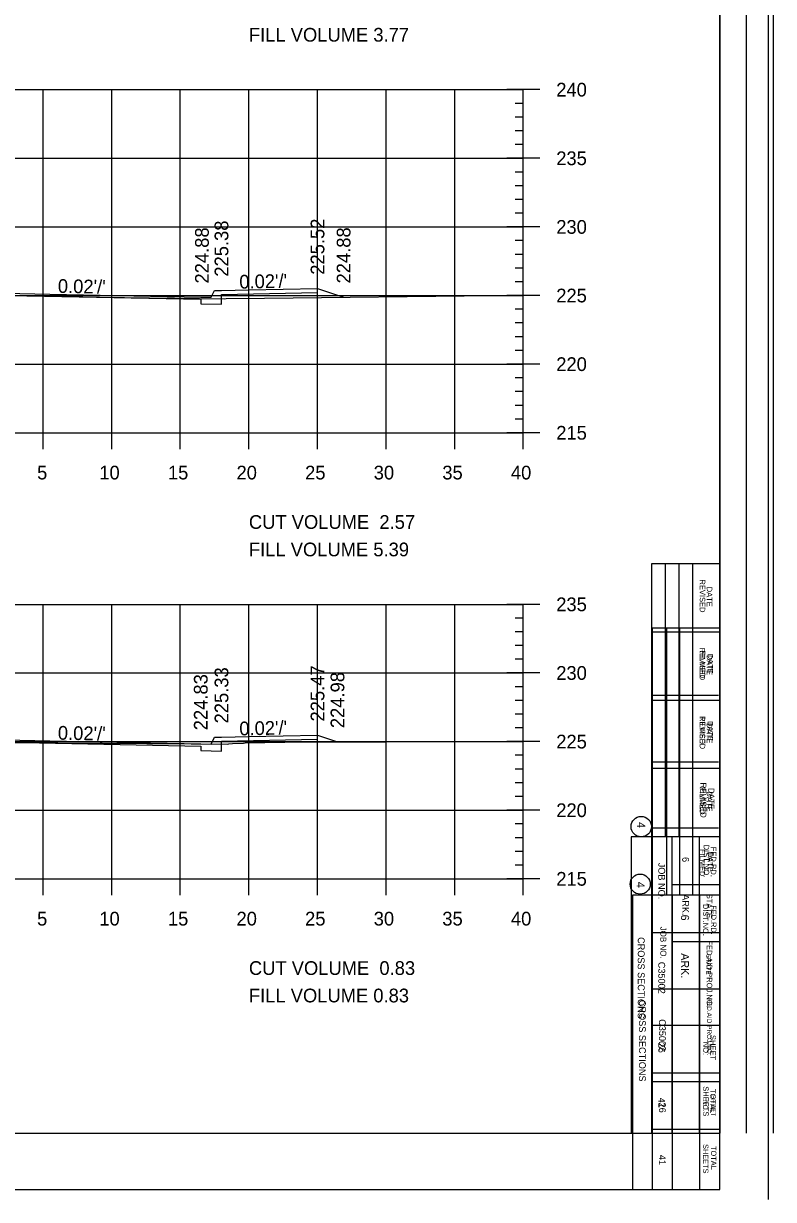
# Model space of a CAD drawing. Extents: x 1367903 to 1373764, y 376865 to 382130.
# Drawn here: x 1370086.4 to 1370195.7, y 377279.1 to 377450.5 of the extents above; entities that cross this region are included whole.
import ezdxf

# ---------------------------------------------------------------- set-up
doc = ezdxf.new("R2010")
doc.units = 0
for name, color, linetype in [('R_Axis', 7, 'Continuous'), ('R_Axis Annot', 7, 'Continuous'), ('R_Border', 7, 'Continuous'), ('R_Border Notes', 7, 'Continuous'), ('R_Border PE', 7, 'Continuous'), ('R_Exist Surface', 7, 'Continuous'), ('R_Fin Surface', 7, 'Continuous'), ('R_Fin Surface Annot', 7, 'Continuous'), ('R_Grid', 7, 'Continuous')]:
    doc.layers.add(name, color=color, linetype=linetype)

msp = doc.modelspace()

# ---------------------------------------------------------------- linework, layer by layer
for points in [[(1370043.22, 377411.59), (1370043.22, 377410.92), (1370043.22, 377410.92), (1370043.22, 377409.56), (1370046.22, 377409.62), (1370046.22, 377410.29), (1370079.22, 377410.95), (1370112.22, 377410.29), (1370112.22, 377409.62), (1370115.22, 377409.56), (1370115.22, 377411), (1370129.22, 377411.28), (1370129.22, 377411.87)], [(1370043.22, 377346.49), (1370043.22, 377345.82), (1370043.22, 377345.82), (1370043.22, 377344.46), (1370046.22, 377344.52), (1370046.22, 377345.18), (1370079.22, 377345.84), (1370112.22, 377345.18), (1370112.22, 377344.52), (1370115.22, 377344.46), (1370115.22, 377345.9), (1370129.22, 377346.18), (1370129.22, 377346.77)]]:
    msp.add_lwpolyline(points)
at = {"layer": 'R_Axis'}
for p, q in [((1370161.62, 377440.84), (1370156.82, 377440.84)), ((1370159.22, 377390.84), (1370159.22, 377440.84)), ((1370159.22, 377438.84), (1370158.02, 377438.84)), ((1370159.22, 377436.84), (1370158.02, 377436.84)), ((1370159.22, 377434.84), (1370158.02, 377434.84)), ((1370159.22, 377432.84), (1370158.02, 377432.84)), ((1370161.62, 377430.84), (1370156.82, 377430.84)), ((1370159.22, 377428.84), (1370158.02, 377428.84)), ((1370159.22, 377426.84), (1370158.02, 377426.84)), ((1370159.22, 377424.84), (1370158.02, 377424.84)), ((1370159.22, 377422.84), (1370158.02, 377422.84)), ((1370161.62, 377420.84), (1370156.82, 377420.84)), ((1370159.22, 377418.84), (1370158.02, 377418.84)), ((1370159.22, 377416.84), (1370158.02, 377416.84)), ((1370159.22, 377414.84), (1370158.02, 377414.84)), ((1370159.22, 377412.84), (1370158.02, 377412.84)), ((1370161.62, 377410.84), (1370156.82, 377410.84)), ((1370159.22, 377408.84), (1370158.02, 377408.84)), ((1370159.22, 377406.84), (1370158.02, 377406.84)), ((1370159.22, 377404.84), (1370158.02, 377404.84)), ((1370159.22, 377402.84), (1370158.02, 377402.84)), ((1370161.62, 377400.84), (1370156.82, 377400.84)), ((1370159.22, 377398.84), (1370158.02, 377398.84)), ((1370159.22, 377396.84), (1370158.02, 377396.84)), ((1370159.22, 377394.84), (1370158.02, 377394.84)), ((1370089.22, 377388.44), (1370089.22, 377393.24)), ((1370099.22, 377388.44), (1370099.22, 377393.24)), ((1370109.22, 377388.44), (1370109.22, 377393.24)), ((1370119.22, 377388.44), (1370119.22, 377393.24)), ((1370129.22, 377388.44), (1370129.22, 377393.24)), ((1370139.22, 377388.44), (1370139.22, 377393.24)), ((1370149.22, 377388.44), (1370149.22, 377393.24)), ((1370159.22, 377388.44), (1370159.22, 377393.24)), ((1370159.22, 377392.84), (1370158.02, 377392.84)), ((1369999.22, 377390.84), (1370159.22, 377390.84)), ((1370161.62, 377390.84), (1370156.82, 377390.84)), ((1370161.62, 377365.84), (1370156.82, 377365.84)), ((1370159.22, 377325.84), (1370159.22, 377365.84)), ((1370159.22, 377363.84), (1370158.02, 377363.84)), ((1370159.22, 377361.84), (1370158.02, 377361.84)), ((1370159.22, 377359.84), (1370158.02, 377359.84)), ((1370159.22, 377357.84), (1370158.02, 377357.84)), ((1370161.62, 377355.84), (1370156.82, 377355.84)), ((1370159.22, 377353.84), (1370158.02, 377353.84)), ((1370159.22, 377351.84), (1370158.02, 377351.84)), ((1370159.22, 377349.84), (1370158.02, 377349.84)), ((1370159.22, 377347.84), (1370158.02, 377347.84)), ((1370161.62, 377345.84), (1370156.82, 377345.84)), ((1370159.22, 377343.84), (1370158.02, 377343.84)), ((1370159.22, 377341.84), (1370158.02, 377341.84)), ((1370159.22, 377339.84), (1370158.02, 377339.84)), ((1370159.22, 377337.84), (1370158.02, 377337.84)), ((1370161.62, 377335.84), (1370156.82, 377335.84)), ((1370159.22, 377333.84), (1370158.02, 377333.84)), ((1370159.22, 377331.84), (1370158.02, 377331.84)), ((1370159.22, 377329.84), (1370158.02, 377329.84)), ((1370089.22, 377323.44), (1370089.22, 377328.24)), ((1370099.22, 377323.44), (1370099.22, 377328.24)), ((1370109.22, 377323.44), (1370109.22, 377328.24)), ((1370119.22, 377323.44), (1370119.22, 377328.24)), ((1370129.22, 377323.44), (1370129.22, 377328.24)), ((1370139.22, 377323.44), (1370139.22, 377328.24)), ((1370149.22, 377323.44), (1370149.22, 377328.24)), ((1370159.22, 377327.84), (1370158.02, 377327.84)), ((1370159.22, 377323.44), (1370159.22, 377328.24)), ((1369999.22, 377325.84), (1370159.22, 377325.84)), ((1370161.62, 377325.84), (1370156.82, 377325.84))]:
    msp.add_line(p, q, dxfattribs=at)
at = {"layer": 'R_Border'}
for p, q in [((1370194.89, 377620.35), (1370194.89, 377279.12)), ((1370187.85, 377280.59), (1370187.85, 377611.47)), ((1370187.85, 377446.03), (1370187.85, 377446.03)), ((1370178.03, 377280.59), (1370178.03, 377362.43)), ((1370178.03, 377362.43), (1370187.85, 377362.43)), ((1370178.03, 377362.43), (1370180.07, 377362.43)), ((1370180.07, 377362.43), (1370180.07, 377323.46)), ((1370182.01, 377362.43), (1370182.01, 377323.46)), ((1370183.87, 377362.43), (1370183.87, 377323.46)), ((1370178.03, 377352.62), (1370187.65, 377352.62)), ((1370178.03, 377342.9), (1370187.65, 377342.9)), ((1370178.03, 377333.27), (1370187.65, 377333.27)), ((1370187.85, 377323.46), (1370175.12, 377323.46)), ((1370175.12, 377323.46), (1370175.12, 377280.59)), ((1370180.95, 377280.59), (1370180.95, 377323.46)), ((1370184.93, 377280.59), (1370184.93, 377323.46)), ((1370187.85, 377316.65), (1370180.95, 377316.65)), ((1370187.85, 377309.75), (1370178.03, 377309.75)), ((1370187.85, 377296.24), (1370178.03, 377296.24)), ((1370187.85, 377289.33), (1370178.03, 377289.33)), ((1369983.52, 377280.59), (1370187.85, 377280.59))]:
    msp.add_line(p, q, dxfattribs=at)
msp.add_circle((1370176.26, 377325.07), 1.46, dxfattribs=at)
at = {"layer": 'R_Border PE'}
for p, q in [((1370191.77, 377288.8), (1370191.77, 377610.76)), ((1370195.69, 377288.8), (1370195.69, 377610.76)), ((1370187.85, 377603.25), (1370187.85, 377288.8)), ((1370177.9, 377371.74), (1370177.9, 377288.8)), ((1370187.85, 377371.74), (1370177.9, 377371.74)), ((1370179.89, 377371.74), (1370179.89, 377331.96)), ((1370181.88, 377371.74), (1370181.88, 377331.96)), ((1370183.87, 377371.74), (1370183.87, 377331.96)), ((1370187.85, 377361.8), (1370177.9, 377361.8)), ((1370187.85, 377351.85), (1370177.9, 377351.85)), ((1370187.85, 377341.91), (1370177.9, 377341.91)), ((1370187.85, 377331.96), (1370174.92, 377331.96)), ((1370174.92, 377331.96), (1370174.92, 377288.8)), ((1370180.88, 377331.96), (1370180.88, 377288.8)), ((1370184.86, 377331.96), (1370184.86, 377288.8)), ((1370180.95, 377325), (1370187.85, 377325)), ((1370178.03, 377318.04), (1370187.85, 377318.04)), ((1370178.03, 377304.51), (1370187.85, 377304.51)), ((1370178.03, 377297.55), (1370187.85, 377297.55)), ((1369983.52, 377288.8), (1370187.85, 377288.8)), ((1370184.96, 377288.8), (1370184.96, 377288.8))]:
    msp.add_line(p, q, dxfattribs=at)
msp.add_circle((1370176.41, 377333.45), 1.49, dxfattribs=at)
at = {"layer": 'R_Exist Surface'}
for points in [[(1369999.22, 377411.67), (1370002.15, 377411.76), (1370002.62, 377412.06), (1370013.69, 377412.14), (1370028.18, 377411.51), (1370030.06, 377411.44), (1370032.34, 377411.01), (1370035.74, 377410.69), (1370040.16, 377410.42), (1370045.99, 377409.3), (1370049.48, 377408.57), (1370053.17, 377409.91), (1370054.59, 377410.57), (1370056.15, 377410.54), (1370057.51, 377410.5), (1370072.75, 377410.69), (1370085.29, 377410.84), (1370097.45, 377410.62), (1370115.65, 377410.34), (1370115.9, 377410.39), (1370115.92, 377410.41), (1370121.47, 377410.47), (1370154.8, 377410.86), (1370159.22, 377410.81)], [(1369999.22, 377346.18), (1370008.12, 377346.07), (1370026.5, 377345.88), (1370037.69, 377345.88), (1370046.02, 377345.63), (1370048.84, 377345.53), (1370054.49, 377345.44), (1370057.25, 377345.5), (1370058.38, 377345.42), (1370073.41, 377345.6), (1370084.91, 377345.72), (1370110.8, 377345.53), (1370116.14, 377345.47), (1370116.28, 377345.51), (1370116.81, 377345.58), (1370118.44, 377345.62), (1370118.67, 377345.64), (1370124.46, 377345.77), (1370153.77, 377345.86), (1370159.22, 377345.87)]]:
    msp.add_lwpolyline(points, dxfattribs=at)
at = {"layer": 'R_Fin Surface'}
for points in [[(1370039.78, 377410.44), (1370043.22, 377411.59), (1370044.22, 377411.59), (1370044.72, 377410.59), (1370046.22, 377410.62), (1370068.22, 377411.06), (1370079.22, 377411.28), (1370090.22, 377411.06), (1370112.22, 377410.62), (1370113.72, 377410.59), (1370114.22, 377411.59), (1370115.22, 377411.59), (1370119.22, 377411.67), (1370129.22, 377411.87), (1370133.02, 377410.6)], [(1370041.09, 377345.78), (1370043.22, 377346.49), (1370044.22, 377346.49), (1370044.72, 377345.49), (1370046.22, 377345.52), (1370068.22, 377345.96), (1370079.22, 377346.18), (1370090.22, 377345.96), (1370112.22, 377345.52), (1370113.72, 377345.49), (1370114.22, 377346.49), (1370115.22, 377346.49), (1370119.22, 377346.57), (1370129.22, 377346.77), (1370132.13, 377345.8)]]:
    msp.add_lwpolyline(points, dxfattribs=at)
at = {"layer": 'R_Grid'}
for p, q in [((1369999.22, 377440.84), (1370159.22, 377440.84)), ((1370089.22, 377390.84), (1370089.22, 377440.84)), ((1370099.22, 377390.84), (1370099.22, 377440.84)), ((1370109.22, 377390.84), (1370109.22, 377440.84)), ((1370119.22, 377390.84), (1370119.22, 377440.84)), ((1370129.22, 377390.84), (1370129.22, 377440.84)), ((1370139.22, 377390.84), (1370139.22, 377440.84)), ((1370149.22, 377390.84), (1370149.22, 377440.84)), ((1370159.22, 377390.84), (1370159.22, 377440.84)), ((1369999.22, 377430.84), (1370159.22, 377430.84)), ((1369999.22, 377420.84), (1370159.22, 377420.84)), ((1369999.22, 377410.84), (1370159.22, 377410.84)), ((1369999.22, 377400.84), (1370159.22, 377400.84)), ((1369999.22, 377390.84), (1370159.22, 377390.84)), ((1369999.22, 377365.84), (1370159.22, 377365.84)), ((1370089.22, 377325.84), (1370089.22, 377365.84)), ((1370099.22, 377325.84), (1370099.22, 377365.84)), ((1370109.22, 377325.84), (1370109.22, 377365.84)), ((1370119.22, 377325.84), (1370119.22, 377365.84)), ((1370129.22, 377325.84), (1370129.22, 377365.84)), ((1370139.22, 377325.84), (1370139.22, 377365.84)), ((1370149.22, 377325.84), (1370149.22, 377365.84)), ((1370159.22, 377325.84), (1370159.22, 377365.84)), ((1369999.22, 377355.84), (1370159.22, 377355.84)), ((1369999.22, 377345.84), (1370159.22, 377345.84)), ((1369999.22, 377335.84), (1370159.22, 377335.84)), ((1369999.22, 377325.84), (1370159.22, 377325.84))]:
    msp.add_line(p, q, dxfattribs=at)

# ---------------------------------------------------------------- texts
at = {"layer": 'R_Axis Annot'}
for s, p in [('FILL VOLUME 3.77', (1370119.22, 377447.84)), ('240', (1370164.02, 377439.84)), ('235', (1370164.02, 377429.84)), ('230', (1370164.02, 377419.84)), ('225', (1370164.02, 377409.84)), ('220', (1370164.02, 377399.84)), ('215', (1370164.02, 377389.84)), ('5', (1370088.34, 377384.04)), ('10', (1370097.41, 377384.04)), ('15', (1370107.41, 377384.04)), ('20', (1370117.41, 377384.04)), ('25', (1370127.41, 377384.04)), ('30', (1370137.41, 377384.04)), ('35', (1370147.41, 377384.04)), ('40', (1370157.41, 377384.04)), ('CUT VOLUME  2.57', (1370119.22, 377376.84)), ('FILL VOLUME 5.39', (1370119.22, 377372.84)), ('235', (1370164.02, 377364.84)), ('230', (1370164.02, 377354.84)), ('225', (1370164.02, 377344.84)), ('220', (1370164.02, 377334.84)), ('215', (1370164.02, 377324.84)), ('5', (1370088.34, 377319.04)), ('10', (1370097.41, 377319.04)), ('15', (1370107.41, 377319.04)), ('20', (1370117.41, 377319.04)), ('25', (1370127.41, 377319.04)), ('30', (1370137.41, 377319.04)), ('35', (1370147.41, 377319.04)), ('40', (1370157.41, 377319.04)), ('CUT VOLUME  0.83', (1370119.22, 377311.84)), ('FILL VOLUME 0.83', (1370119.22, 377307.84))]:
    msp.add_text(s, height=2, dxfattribs=at).set_placement(p)
at = {"layer": 'R_Border'}
for s, height, p in [('REVISED', 0.778, (1370184.93, 377359.51)), ('DATE', 0.778, (1370186.1, 377358.64)), ('FILMED', 0.778, (1370184.93, 377349.41)), ('DATE', 0.778, (1370186.1, 377348.82)), ('REVISED', 0.875, (1370185.03, 377339.88)), ('DATE', 0.875, (1370186.2, 377339.1)), ('FILMED', 0.778, (1370184.93, 377330.16)), ('DATE', 0.778, (1370186.1, 377329.77)), ('4', 1.17, (1370175.74, 377325.4)), ('DIST.NO.', 0.778, (1370185.42, 377322.19)), ('FED.RD.', 0.778, (1370186.59, 377321.99)), ('6', 1.17, (1370182.21, 377320.63)), ('JOB NO.', 0.875, (1370179.2, 377318.88)), ('ARK.', 1.166, (1370182.21, 377315)), ('STATE', 0.681, (1370185.9, 377314.9)), ('FED.AID PROJ.NO.', 0.6805, (1370186, 377308.49)), ('SHEET', 0.681, (1370186.59, 377294.39)), ('NO.', 0.681, (1370185.42, 377293.61)), ('SHEETS', 0.778, (1370185.42, 377287.2)), ('TOTAL', 0.778, (1370186.59, 377286.91))]:
    msp.add_text(s, height=height, rotation=270, dxfattribs=at).set_placement(p)
at = {"layer": 'R_Border Notes'}
for s, height, p in [('CROSS SECTIONS', 0.9945, (1370176.08, 377308.2)), ('C35002', 0.995, (1370178.99, 377305.39)), ('26', 0.995, (1370179, 377293.24)), ('41', 0.995, (1370178.99, 377285.62))]:
    msp.add_text(s, height=height, rotation=270, dxfattribs=at).set_placement(p)
at = {"layer": 'R_Border PE'}
for s, height, p in [('REVISED', 0.796, (1370184.94, 377369.47)), ('DATE', 0.796, (1370185.97, 377368.41)), ('FILMED', 0.796, (1370184.94, 377359.12)), ('DATE', 0.796, (1370185.97, 377358.47)), ('REVISED', 0.796, (1370184.94, 377349.57)), ('DATE', 0.796, (1370185.97, 377348.52)), ('FILMED', 0.796, (1370184.94, 377339.23)), ('DATE', 0.796, (1370185.97, 377338.58)), ('4', 1.19, (1370175.81, 377334.12)), ('DIST.NO.', 0.796, (1370185.52, 377330.83)), ('FED.RD.', 0.796, (1370186.55, 377330.52)), ('JOB NO.', 0.995, (1370178.9, 377328.19)), ('6', 0.995, (1370182.38, 377329.02)), ('ARK.', 0.995, (1370182.38, 377323.6)), ('STATE', 0.796, (1370185.96, 377323.66)), ('CROSS SECTIONS', 0.9945, (1370175.91, 377317.35)), ('FED.AID PROJ.NO.', 0.7956, (1370185.96, 377316.88)), ('C35002', 0.995, (1370178.9, 377313.75)), ('SHEET', 0.796, (1370186.47, 377303.09)), ('26', 0.995, (1370178.9, 377301.97)), ('NO.', 0.796, (1370185.44, 377302.11)), ('SHEETS', 0.796, (1370185.44, 377295.62)), ('41', 0.995, (1370178.9, 377293.96)), ('TOTAL', 0.796, (1370186.47, 377295.23))]:
    msp.add_text(s, height=height, rotation=270, dxfattribs=at).set_placement(p)
at = {"layer": 'R_Fin Surface Annot'}
for s, rotation, p in [('224.88', 90, (1370113.37, 377412.59)), ('225.38', 90, (1370116.22, 377413.59)), ('225.52', 90, (1370130.22, 377413.87)), ('224.88', 90, (1370134.02, 377412.6)), ("0.02'/'", 1.1458, (1370117.84, 377411.84)), ("0.02'/'", 358.8542, (1370091.35, 377411.24)), ('224.83', 90, (1370113.2, 377347.49)), ('225.33', 90, (1370116.22, 377348.49)), ('225.47', 90, (1370130.22, 377348.77)), ('224.98', 90, (1370133.13, 377347.8)), ("0.02'/'", 1.1458, (1370117.84, 377346.74)), ("0.02'/'", 358.8542, (1370091.35, 377346.13))]:
    msp.add_text(s, height=2, rotation=rotation, dxfattribs=at).set_placement(p)

doc.saveas('drawing.dxf')
